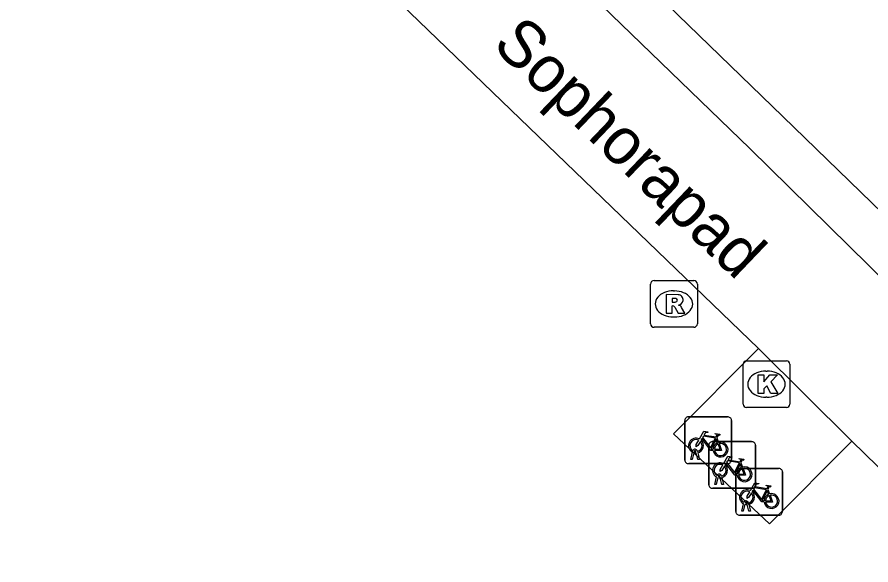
# Model space of a CAD drawing. Extents: x 162347 to 162868, y 381221 to 381813.
# Drawn here: x 162652.29 to 162670.57, y 381592.81 to 381604.54 of the extents above; entities that cross this region are included whole.
import ezdxf

# ---------------------------------------------------------------- set-up
doc = ezdxf.new("R2010")
doc.units = 0
for name, color, linetype in [('IMGEO_Fietsenrek', 7, 'Continuous'), ('IMGEO_Kolk', 7, 'Continuous'), ('IMGEO_Openbare_ruimte_label', 7, 'Continuous'), ('IMGEO_Pand', 7, 'Continuous'), ('IMGEO_Rioolput', 7, 'Continuous'), ('IMGEO_Voetpad_open', 7, 'Continuous')]:
    doc.layers.add(name, color=color, linetype=linetype)

msp = doc.modelspace()

# ---------------------------------------------------------------- linework, layer by layer
at = {"layer": 'IMGEO_Fietsenrek'}
for p, q in [((162666.582, 381595.055), (162666.582, 381595.896)), ((162666.582, 381595.896), (162666.582, 381595.055)), ((162666.657, 381595.98), (162667.498, 381595.98)), ((162667.498, 381595.98), (162666.657, 381595.98)), ((162667.582, 381595.905), (162667.582, 381595.064)), ((162667.582, 381595.064), (162667.582, 381595.905)), ((162667.269, 381595.529), (162667.305, 381595.434)), ((162667.096, 381594.524), (162667.096, 381595.365)), ((162667.096, 381595.365), (162667.096, 381594.524)), ((162667.171, 381595.449), (162668.012, 381595.449)), ((162668.012, 381595.449), (162667.171, 381595.449)), ((162668.096, 381595.374), (162668.096, 381594.533)), ((162668.096, 381594.533), (162668.096, 381595.374)), ((162666.709, 381595.064), (162666.748, 381595.224)), ((162666.778, 381595.212), (162666.743, 381595.064)), ((162666.82, 381595.236), (162666.819, 381595.24)), ((162666.861, 381595.064), (162666.827, 381595.206)), ((162666.851, 381595.247), (162666.852, 381595.24)), ((162666.859, 381595.21), (162666.894, 381595.064)), ((162667.507, 381594.98), (162666.666, 381594.98)), ((162666.666, 381594.98), (162667.507, 381594.98)), ((162666.743, 381595.064), (162666.709, 381595.064)), ((162666.894, 381595.064), (162666.861, 381595.064)), ((162667.783, 381594.998), (162667.819, 381594.903)), ((162667.674, 381593.95), (162667.674, 381594.791)), ((162667.674, 381594.791), (162667.674, 381593.95)), ((162667.749, 381594.875), (162668.59, 381594.875)), ((162668.59, 381594.875), (162667.749, 381594.875)), ((162668.674, 381594.8), (162668.674, 381593.959)), ((162668.674, 381593.959), (162668.674, 381594.8)), ((162667.223, 381594.533), (162667.262, 381594.693)), ((162667.292, 381594.681), (162667.257, 381594.533)), ((162667.334, 381594.705), (162667.333, 381594.709)), ((162667.375, 381594.533), (162667.341, 381594.675)), ((162667.365, 381594.716), (162667.366, 381594.709)), ((162667.373, 381594.679), (162667.408, 381594.533)), ((162668.021, 381594.449), (162667.18, 381594.449)), ((162667.18, 381594.449), (162668.021, 381594.449)), ((162667.257, 381594.533), (162667.223, 381594.533)), ((162667.408, 381594.533), (162667.375, 381594.533)), ((162668.361, 381594.424), (162668.397, 381594.329)), ((162667.801, 381593.959), (162667.84, 381594.119)), ((162667.87, 381594.107), (162667.835, 381593.959)), ((162667.912, 381594.131), (162667.911, 381594.135)), ((162667.953, 381593.959), (162667.919, 381594.101)), ((162667.943, 381594.142), (162667.944, 381594.135)), ((162667.951, 381594.105), (162667.986, 381593.959)), ((162668.599, 381593.875), (162667.758, 381593.875)), ((162667.758, 381593.875), (162668.599, 381593.875)), ((162667.835, 381593.959), (162667.801, 381593.959)), ((162667.986, 381593.959), (162667.953, 381593.959))]:
    msp.add_line(p, q, dxfattribs=at)
for points in [[(162666.895, 381595.506), (162666.99, 381595.67), (162667.076, 381595.656), (162667.078, 381595.647), (162667.022, 381595.636), (162666.995, 381595.591), (162667.251, 381595.55)], [(162667.191, 381595.262), (162667.141, 381595.262), (162666.95, 381595.513), (162666.931, 381595.481)], [(162667.238, 381595.525), (162666.981, 381595.566), (162666.964, 381595.537), (162667.131, 381595.317), (162667.238, 381595.525)], [(162667.286, 381595.427), (162667.256, 381595.504), (162667.147, 381595.286), (162667.19, 381595.286)], [(162667.251, 381595.55), (162667.276, 381595.599), (162667.27, 381595.603), (162667.247, 381595.607), (162667.235, 381595.614), (162667.234, 381595.617), (162667.236, 381595.622), (162667.331, 381595.607), (162667.333, 381595.597), (162667.323, 381595.584), (162667.311, 381595.578), (162667.297, 381595.584), (162667.269, 381595.529)], [(162666.916, 381595.454), (162666.864, 381595.364), (162666.824, 381595.339), (162666.825, 381595.386), (162666.88, 381595.48)], [(162667.22, 381595.286), (162667.34, 381595.285), (162667.296, 381595.399)], [(162667.316, 381595.406), (162667.371, 381595.261), (162667.221, 381595.261)], [(162667.409, 381594.975), (162667.504, 381595.139), (162667.59, 381595.125), (162667.592, 381595.116), (162667.536, 381595.105), (162667.509, 381595.06), (162667.765, 381595.019)], [(162667.705, 381594.731), (162667.655, 381594.731), (162667.464, 381594.982), (162667.445, 381594.95)], [(162667.752, 381594.994), (162667.495, 381595.035), (162667.478, 381595.006), (162667.645, 381594.786), (162667.752, 381594.994)], [(162667.8, 381594.896), (162667.77, 381594.973), (162667.661, 381594.755), (162667.704, 381594.755)], [(162667.765, 381595.019), (162667.79, 381595.068), (162667.784, 381595.072), (162667.761, 381595.076), (162667.749, 381595.083), (162667.748, 381595.086), (162667.75, 381595.091), (162667.845, 381595.076), (162667.847, 381595.066), (162667.837, 381595.053), (162667.825, 381595.047), (162667.811, 381595.053), (162667.783, 381594.998)], [(162667.43, 381594.923), (162667.378, 381594.833), (162667.338, 381594.808), (162667.339, 381594.855), (162667.394, 381594.949)], [(162667.734, 381594.755), (162667.854, 381594.754), (162667.81, 381594.868)], [(162667.83, 381594.875), (162667.885, 381594.73), (162667.735, 381594.73)], [(162667.987, 381594.401), (162668.082, 381594.565), (162668.168, 381594.551), (162668.17, 381594.542), (162668.114, 381594.531), (162668.087, 381594.486), (162668.343, 381594.445)], [(162668.283, 381594.157), (162668.233, 381594.157), (162668.042, 381594.408), (162668.023, 381594.376)], [(162668.33, 381594.42), (162668.073, 381594.461), (162668.056, 381594.432), (162668.223, 381594.212), (162668.33, 381594.42)], [(162668.343, 381594.445), (162668.368, 381594.494), (162668.362, 381594.498), (162668.339, 381594.502), (162668.327, 381594.509), (162668.326, 381594.512), (162668.328, 381594.517), (162668.423, 381594.502), (162668.425, 381594.492), (162668.415, 381594.479), (162668.403, 381594.473), (162668.389, 381594.479), (162668.361, 381594.424)], [(162668.008, 381594.349), (162667.956, 381594.259), (162667.916, 381594.234), (162667.917, 381594.281), (162667.972, 381594.375)], [(162668.378, 381594.322), (162668.348, 381594.399), (162668.239, 381594.181), (162668.282, 381594.181)], [(162668.312, 381594.181), (162668.432, 381594.18), (162668.388, 381594.294)], [(162668.408, 381594.301), (162668.463, 381594.156), (162668.313, 381594.156)]]:
    msp.add_lwpolyline(points, dxfattribs=at)
for centre, radius, start, end in [((162666.66, 381595.902), 0.0779, 92.4484, 184.2845), ((162666.66, 381595.902), 0.0779, 92.4484, 184.2845), ((162667.504, 381595.902), 0.0779, 2.4484, 94.2845), ((162667.504, 381595.902), 0.0779, 2.4484, 94.2845), ((162666.822, 381595.365), 0.159, 62.6766, 242.1369), ((162666.822, 381595.365), 0.129, 63.3192, 238.903), ((162666.822, 381595.365), 0.129, 283.6043, 43.4302), ((162666.822, 381595.365), 0.159, 283.5766, 46.6042), ((162667.174, 381595.371), 0.0779, 92.4484, 184.2845), ((162667.174, 381595.371), 0.0779, 92.4484, 184.2845), ((162667.349, 381595.281), 0.159, 113.3408, 178.3217), ((162667.349, 381595.281), 0.159, 187.0065, 105.7708), ((162667.349, 381595.281), 0.129, 113.923, 177.9556), ((162667.349, 381595.281), 0.129, 188.6715, 104.5883), ((162668.018, 381595.371), 0.0779, 2.4484, 94.2845), ((162668.018, 381595.371), 0.0779, 2.4484, 94.2845), ((162666.802, 381595.236), 0.0499, 12.8025, 158.6934), ((162666.822, 381595.365), 0.159, 253.9967, 271.7867), ((162666.802, 381595.236), 0.0174, 12.8025, 163.4502), ((162666.822, 381595.365), 0.129, 253.415, 269.0204), ((162666.66, 381595.058), 0.0779, 182.4484, 274.2845), ((162666.66, 381595.058), 0.0779, 182.4484, 274.2845), ((162667.336, 381594.834), 0.159, 62.6766, 242.1369), ((162667.336, 381594.834), 0.129, 63.3192, 238.903), ((162667.504, 381595.058), 0.0779, 272.4484, 4.2845), ((162667.504, 381595.058), 0.0779, 272.4484, 4.2845), ((162667.336, 381594.834), 0.129, 283.6043, 43.4302), ((162667.336, 381594.834), 0.159, 283.5766, 46.6042), ((162667.752, 381594.797), 0.0779, 92.4484, 184.2845), ((162667.752, 381594.797), 0.0779, 92.4484, 184.2845), ((162667.863, 381594.75), 0.159, 113.3408, 178.3217), ((162667.863, 381594.75), 0.159, 187.0065, 105.7708), ((162667.863, 381594.75), 0.129, 113.923, 177.9556), ((162667.863, 381594.75), 0.129, 188.6715, 104.5883), ((162668.596, 381594.797), 0.0779, 2.4484, 94.2845), ((162668.596, 381594.797), 0.0779, 2.4484, 94.2845), ((162667.316, 381594.705), 0.0499, 12.8025, 158.6934), ((162667.336, 381594.834), 0.159, 253.9967, 271.7867), ((162667.316, 381594.705), 0.0174, 12.8025, 163.4502), ((162667.336, 381594.834), 0.129, 253.415, 269.0204), ((162667.174, 381594.527), 0.0779, 182.4484, 274.2845), ((162667.174, 381594.527), 0.0779, 182.4484, 274.2845), ((162667.914, 381594.26), 0.159, 62.6766, 242.1369), ((162668.018, 381594.527), 0.0779, 272.4484, 4.2845), ((162668.018, 381594.527), 0.0779, 272.4484, 4.2845), ((162667.914, 381594.26), 0.129, 63.3192, 238.903), ((162667.914, 381594.26), 0.129, 283.6043, 43.4302), ((162667.914, 381594.26), 0.159, 283.5766, 46.6042), ((162668.441, 381594.176), 0.159, 113.3408, 178.3217), ((162668.441, 381594.176), 0.159, 187.0065, 105.7708), ((162668.441, 381594.176), 0.129, 113.923, 177.9556), ((162668.441, 381594.176), 0.129, 188.6715, 104.5883), ((162667.894, 381594.131), 0.0499, 12.8025, 158.6934), ((162667.914, 381594.26), 0.159, 253.9967, 271.7867), ((162667.894, 381594.131), 0.0174, 12.8025, 163.4502), ((162667.914, 381594.26), 0.129, 253.415, 269.0204), ((162667.752, 381593.953), 0.0779, 182.4484, 274.2845), ((162667.752, 381593.953), 0.0779, 182.4484, 274.2845), ((162668.596, 381593.953), 0.0779, 272.4484, 4.2845), ((162668.596, 381593.953), 0.0779, 272.4484, 4.2845)]:
    msp.add_arc(centre, radius, start, end, dxfattribs=at)
at = {"layer": 'IMGEO_Kolk'}
for p, q in [((162667.905, 381597.18), (162668.757, 381597.18)), ((162667.83, 381596.254), (162667.83, 381597.106)), ((162668.831, 381597.106), (162668.831, 381596.254)), ((162668.318, 381596.96), (162668.343, 381596.96)), ((162668.341, 381596.4), (162668.316, 381596.4)), ((162668.757, 381596.18), (162667.905, 381596.18))]:
    msp.add_line(p, q, dxfattribs=at)
for points in [[(162667.905, 381597.18), (162668.757, 381597.18)], [(162667.83, 381596.254), (162667.83, 381597.106)], [(162668.831, 381597.106), (162668.831, 381596.254)], [(162668.151, 381596.88), (162668.274, 381596.88), (162668.274, 381596.729), (162668.404, 381596.88), (162668.568, 381596.88), (162668.422, 381596.729), (162668.575, 381596.48), (162668.423, 381596.48), (162668.338, 381596.644), (162668.274, 381596.577), (162668.274, 381596.48), (162668.151, 381596.48), (162668.151, 381596.88)], [(162668.757, 381596.18), (162667.905, 381596.18)]]:
    msp.add_lwpolyline(points, dxfattribs=at)
for centre, start, end in [((162667.907, 381597.104), 91.552, 178.448), ((162667.907, 381597.104), 91.552, 178.448), ((162668.755, 381597.104), 1.552, 88.448), ((162668.755, 381597.104), 1.552, 88.448), ((162667.907, 381596.256), 181.552, 268.448), ((162667.907, 381596.256), 181.552, 268.448), ((162668.755, 381596.256), 271.552, 358.448), ((162668.755, 381596.256), 271.552, 358.448)]:
    msp.add_arc(centre, 0.0765, start, end, dxfattribs=at)
for centre, major_axis, ratio, start_param, end_param in [((162668.317, 381596.68), (-0.387, 0.002), 0.722429, 4.712389, 7.853982), ((162668.342, 381596.68), (-0.39, 0.002), 0.717154, 1.570796, 4.712389)]:
    msp.add_ellipse(centre, major_axis=major_axis, ratio=ratio, start_param=start_param, end_param=end_param, dxfattribs=at)
at = {"layer": 'IMGEO_Pand'}
msp.add_lwpolyline([(162665.532, 381605.474), (162668.681, 381602.417), (162675.103, 381596.183), (162678.089, 381593.285)], dxfattribs=at)
at = {"layer": 'IMGEO_Rioolput'}
for p, q in [((162665.85, 381597.973), (162665.85, 381598.825)), ((162665.925, 381598.899), (162666.777, 381598.899)), ((162666.851, 381598.825), (162666.851, 381597.973)), ((162666.338, 381598.679), (162666.363, 381598.679)), ((162666.361, 381598.119), (162666.336, 381598.119)), ((162666.777, 381597.899), (162665.925, 381597.899))]:
    msp.add_line(p, q, dxfattribs=at)
for points in [[(162665.85, 381597.973), (162665.85, 381598.825)], [(162665.925, 381598.899), (162666.777, 381598.899)], [(162666.851, 381598.825), (162666.851, 381597.973)], [(162666.439, 381598.597), (162666.187, 381598.599), (162666.187, 381598.199)], [(162666.365, 381598.518), (162666.311, 381598.518), (162666.311, 381598.437)], [(162666.311, 381598.437), (162666.363, 381598.437)], [(162666.187, 381598.199), (162666.311, 381598.199), (162666.311, 381598.361), (162666.322, 381598.361)], [(162666.369, 381598.332), (162666.44, 381598.199), (162666.58, 381598.199), (162666.515, 381598.325)], [(162666.777, 381597.899), (162665.925, 381597.899)]]:
    msp.add_lwpolyline(points, dxfattribs=at)
for centre, radius, start, end in [((162665.927, 381598.823), 0.0765, 91.552, 178.448), ((162665.927, 381598.823), 0.0765, 91.552, 178.448), ((162666.775, 381598.823), 0.0765, 1.552, 88.448), ((162666.775, 381598.823), 0.0765, 1.552, 88.448), ((162666.347, 381598.626), 0.19, 274.7715, 282.9687), ((162666.371, 381598.422), 0.0964, 77.0061, 93.1865), ((162666.385, 381598.479), 0.0378, 276.6634, 79.6772), ((162666.438, 381598.487), 0.109, 350.3612, 89.416), ((162666.436, 381598.487), 0.112, 277.5842, 350.9817), ((162666.321, 381598.308), 0.0533, 26.0293, 88.6989), ((162666.42, 381598.272), 0.108, 29.5134, 73.7905), ((162665.927, 381597.975), 0.0765, 181.552, 268.448), ((162665.927, 381597.975), 0.0765, 181.552, 268.448), ((162666.775, 381597.975), 0.0765, 271.552, 358.448), ((162666.775, 381597.975), 0.0765, 271.552, 358.448)]:
    msp.add_arc(centre, radius, start, end, dxfattribs=at)
for centre, major_axis, ratio, start_param, end_param in [((162666.337, 381598.399), (-0.387, 0.002), 0.722429, 4.712389, 7.853982), ((162666.362, 381598.399), (-0.39, 0.002), 0.717154, 1.570796, 4.712389)]:
    msp.add_ellipse(centre, major_axis=major_axis, ratio=ratio, start_param=start_param, end_param=end_param, dxfattribs=at)
at = {"layer": 'IMGEO_Voetpad_open'}
for points in [[(162689.987, 381580.301), (162686.832, 381583.418), (162680.473, 381589.574), (162674.343, 381595.464), (162667.976, 381601.726), (162661.834, 381607.667), (162655.527, 381613.812), (162652.285, 381616.955)], [(162656.566, 381608.626), (162668.158, 381597.447)], [(162670.159, 381595.461), (162668.394, 381593.687), (162666.339, 381595.619), (162668.158, 381597.447)], [(162668.158, 381597.447), (162670.159, 381595.461)], [(162670.159, 381595.461), (162680.565, 381585.323)]]:
    msp.add_lwpolyline(points, dxfattribs=at)

# ---------------------------------------------------------------- texts
at = {"layer": 'IMGEO_Openbare_ruimte_label'}
msp.add_text('Sophorapad', height=1, rotation=316.2964, dxfattribs=at).set_placement((162662.435, 381603.917))

doc.saveas('drawing.dxf')
